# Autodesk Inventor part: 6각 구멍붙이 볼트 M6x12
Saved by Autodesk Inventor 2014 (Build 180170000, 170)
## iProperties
Created: 2026-01
Part Number: 6각 구멍붙이 볼트 M6x12
Material: 일반
Document SubType Name: Modeling
Designer: dg
Density: 1 g/cm^3
Appearance: 기본값
Author: dg
Author: jhkim
Description: 6각머리 태핑 나사
Creation Date: 2026-01-09
Sending System: Autodesk Inventor 2026
Preprocessor: ST-DEVELOPER v20.1
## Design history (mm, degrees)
node "6각 구멍붙이 볼트 M6x121"
body "Solid1"
node "기준1"
